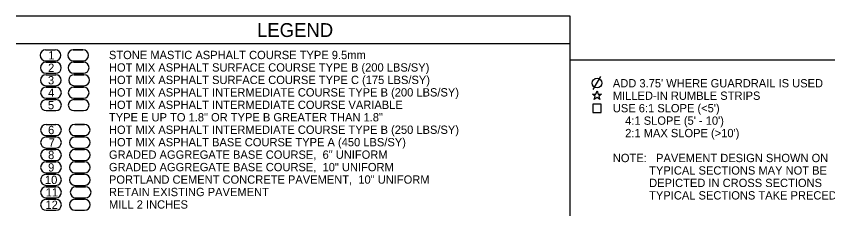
# Model space of a CAD drawing. Extents: x 2003207 to 2014043, y 843846 to 860154.
# Drawn here: x 2013805.7 to 2013864.3, y 844686 to 844700.4 of the extents above; entities that cross this region are included whole.
import ezdxf

# ---------------------------------------------------------------- set-up
doc = ezdxf.new("R2010")
doc.units = 0
for name, color, linetype in [('RD_EX_Road', 7, 'Continuous'), ('RD_EX_Road_txCode', 7, 'Continuous'), ('RD_QTY_ConcPave', 7, 'Continuous'), ('RD_QTY_Intermediate', 7, 'Continuous'), ('RD_QTY_Milling', 7, 'Continuous'), ('RD_QTY_Surf_Course', 7, 'Continuous'), ('RD_SHT_Bndy', 7, 'Continuous'), ('RD_TX_Misc2', 7, 'Continuous')]:
    doc.layers.add(name, color=color, linetype=linetype)

msp = doc.modelspace()

# ---------------------------------------------------------------- linework, layer by layer
at = {"layer": 'RD_EX_Road'}
for p, q in [((2013810.723, 844688.087), (2013810.023, 844688.087)), ((2013810.661, 844687.187), (2013809.961, 844687.187)), ((2013810.023, 844687.287), (2013810.723, 844687.287)), ((2013809.961, 844686.387), (2013810.661, 844686.387))]:
    msp.add_line(p, q, dxfattribs=at)
for centre, start, end in [((2013810.023, 844687.687), 90, 270), ((2013810.723, 844687.687), 270, 90), ((2013809.961, 844686.787), 90, 270), ((2013810.661, 844686.787), 270, 90)]:
    msp.add_arc(centre, 0.4, start, end, dxfattribs=at)
at = {"layer": 'RD_EX_Road_txCode'}
msp.add_line((2013847.384, 844695.107), (2013847.95, 844696.05), dxfattribs=at)
for points in [[(2013847.335, 844694.786), (2013847.589, 844694.786), (2013847.667, 844695.028), (2013847.746, 844694.786), (2013848, 844694.786), (2013847.795, 844694.637), (2013847.873, 844694.395), (2013847.667, 844694.544), (2013847.462, 844694.395), (2013847.54, 844694.637)], [(2013847.367, 844693.452), (2013847.967, 844693.452), (2013847.967, 844694.052), (2013847.367, 844694.052)]]:
    msp.add_lwpolyline(points, close=True, dxfattribs=at)
msp.add_circle((2013847.667, 844695.578), 0.35, dxfattribs=at)
at = {"layer": 'RD_QTY_ConcPave'}
for p, q in [((2013810.661, 844690.787), (2013809.961, 844690.787)), ((2013809.961, 844689.987), (2013810.661, 844689.987)), ((2013810.661, 844689.887), (2013809.961, 844689.887)), ((2013809.961, 844689.087), (2013810.661, 844689.087)), ((2013810.661, 844688.987), (2013809.961, 844688.987)), ((2013809.961, 844688.187), (2013810.661, 844688.187))]:
    msp.add_line(p, q, dxfattribs=at)
for centre, start, end in [((2013809.961, 844690.387), 90, 270), ((2013810.661, 844690.387), 270, 90), ((2013809.961, 844689.487), 90, 270), ((2013810.661, 844689.487), 270, 90), ((2013809.961, 844688.587), 90, 270), ((2013810.661, 844688.587), 270, 90)]:
    msp.add_arc(centre, 0.4, start, end, dxfattribs=at)
at = {"layer": 'RD_QTY_Intermediate'}
for p, q in [((2013810.582, 844695.287), (2013809.882, 844695.287)), ((2013809.882, 844694.487), (2013810.582, 844694.487)), ((2013810.582, 844694.387), (2013809.882, 844694.387)), ((2013809.882, 844693.587), (2013810.582, 844693.587)), ((2013810.65, 844692.587), (2013809.95, 844692.587)), ((2013809.95, 844691.787), (2013810.65, 844691.787)), ((2013810.661, 844691.687), (2013809.961, 844691.687)), ((2013809.961, 844690.887), (2013810.661, 844690.887))]:
    msp.add_line(p, q, dxfattribs=at)
for centre, start, end in [((2013809.882, 844694.887), 90, 270), ((2013810.582, 844694.887), 270, 90), ((2013809.882, 844693.987), 90, 270), ((2013810.582, 844693.987), 270, 90), ((2013809.95, 844692.187), 90, 270), ((2013810.65, 844692.187), 270, 90), ((2013809.961, 844691.287), 90, 270), ((2013810.661, 844691.287), 270, 90)]:
    msp.add_arc(centre, 0.4, start, end, dxfattribs=at)
at = {"layer": 'RD_QTY_Milling'}
for p, q in [((2013810.661, 844687.187), (2013809.961, 844687.187)), ((2013809.961, 844686.387), (2013810.661, 844686.387))]:
    msp.add_line(p, q, dxfattribs=at)
for centre, start, end in [((2013809.961, 844686.787), 90, 270), ((2013810.661, 844686.787), 270, 90)]:
    msp.add_arc(centre, 0.4, start, end, dxfattribs=at)
at = {"layer": 'RD_QTY_Surf_Course'}
for p, q in [((2013810.542, 844697.987), (2013809.842, 844697.987)), ((2013809.842, 844697.187), (2013810.542, 844697.187)), ((2013810.576, 844697.087), (2013809.876, 844697.087)), ((2013809.876, 844696.287), (2013810.576, 844696.287)), ((2013810.61, 844696.187), (2013809.91, 844696.187)), ((2013809.91, 844695.387), (2013810.61, 844695.387))]:
    msp.add_line(p, q, dxfattribs=at)
for centre, start, end in [((2013809.842, 844697.587), 90, 270), ((2013810.542, 844697.587), 270, 90), ((2013809.876, 844696.687), 90, 270), ((2013810.576, 844696.687), 270, 90), ((2013809.91, 844695.787), 90, 270), ((2013810.61, 844695.787), 270, 90)]:
    msp.add_arc(centre, 0.4, start, end, dxfattribs=at)
at = {"layer": 'RD_SHT_Bndy'}
for p, q in [((2013845.721, 844700.41), (2013805.721, 844700.41)), ((2013845.721, 844698.41), (2013845.721, 844700.41)), ((2013845.721, 844698.41), (2013805.721, 844698.41)), ((2013845.721, 844685.992), (2013845.721, 844698.41)), ((2013868.755, 844697.242), (2013845.755, 844697.242))]:
    msp.add_line(p, q, dxfattribs=at)
at = {"layer": 'RD_TX_Misc2'}
for p, q in [((2013807.842, 844697.987), (2013808.542, 844697.987)), ((2013809.842, 844697.987), (2013810.542, 844697.987)), ((2013807.842, 844697.187), (2013808.542, 844697.187)), ((2013807.876, 844697.087), (2013808.576, 844697.087)), ((2013809.842, 844697.187), (2013810.542, 844697.187)), ((2013809.876, 844697.087), (2013810.576, 844697.087)), ((2013807.871, 844696.187), (2013808.571, 844696.187)), ((2013807.876, 844696.287), (2013808.576, 844696.287)), ((2013809.876, 844696.287), (2013810.576, 844696.287)), ((2013809.91, 844696.187), (2013810.61, 844696.187)), ((2013807.871, 844695.387), (2013808.571, 844695.387)), ((2013807.882, 844695.287), (2013808.582, 844695.287)), ((2013809.882, 844695.287), (2013810.582, 844695.287)), ((2013809.91, 844695.387), (2013810.61, 844695.387)), ((2013807.882, 844694.487), (2013808.582, 844694.487)), ((2013807.882, 844694.387), (2013808.582, 844694.387)), ((2013809.882, 844694.487), (2013810.582, 844694.487)), ((2013809.882, 844694.387), (2013810.582, 844694.387)), ((2013807.882, 844693.587), (2013808.582, 844693.587)), ((2013809.882, 844693.587), (2013810.582, 844693.587)), ((2013807.882, 844692.587), (2013808.582, 844692.587)), ((2013809.95, 844692.587), (2013810.65, 844692.587)), ((2013807.882, 844691.787), (2013808.582, 844691.787)), ((2013807.882, 844691.687), (2013808.582, 844691.687)), ((2013809.95, 844691.787), (2013810.65, 844691.787)), ((2013809.961, 844691.687), (2013810.661, 844691.687)), ((2013807.882, 844690.887), (2013808.582, 844690.887)), ((2013807.882, 844690.787), (2013808.582, 844690.787)), ((2013809.961, 844690.887), (2013810.661, 844690.887)), ((2013809.961, 844690.787), (2013810.661, 844690.787)), ((2013807.882, 844689.987), (2013808.582, 844689.987)), ((2013807.882, 844689.887), (2013808.582, 844689.887)), ((2013809.961, 844689.987), (2013810.661, 844689.987)), ((2013809.961, 844689.887), (2013810.661, 844689.887)), ((2013807.882, 844689.087), (2013808.582, 844689.087)), ((2013807.882, 844688.987), (2013808.582, 844688.987)), ((2013809.961, 844689.087), (2013810.661, 844689.087)), ((2013809.961, 844688.987), (2013810.661, 844688.987)), ((2013807.882, 844688.187), (2013808.582, 844688.187)), ((2013809.961, 844688.187), (2013810.661, 844688.187)), ((2013807.882, 844688.087), (2013808.582, 844688.087)), ((2013810.023, 844688.087), (2013810.723, 844688.087)), ((2013807.882, 844687.287), (2013808.582, 844687.287)), ((2013807.882, 844687.187), (2013808.582, 844687.187)), ((2013809.961, 844687.187), (2013810.661, 844687.187)), ((2013810.023, 844687.287), (2013810.723, 844687.287)), ((2013807.882, 844686.387), (2013808.582, 844686.387)), ((2013809.961, 844686.387), (2013810.661, 844686.387))]:
    msp.add_line(p, q, dxfattribs=at)
for centre, start, end in [((2013807.842, 844697.587), 90, 270), ((2013808.542, 844697.587), 270, 90), ((2013809.842, 844697.587), 90, 270), ((2013810.542, 844697.587), 270, 90), ((2013807.876, 844696.687), 90, 270), ((2013808.576, 844696.687), 270, 90), ((2013809.876, 844696.687), 90, 270), ((2013810.576, 844696.687), 270, 90), ((2013807.871, 844695.787), 90, 270), ((2013808.571, 844695.787), 270, 90), ((2013809.91, 844695.787), 90, 270), ((2013810.61, 844695.787), 270, 90), ((2013807.882, 844694.887), 90, 270), ((2013808.582, 844694.887), 270, 90), ((2013809.882, 844694.887), 90, 270), ((2013810.582, 844694.887), 270, 90), ((2013807.882, 844693.987), 90, 270), ((2013808.582, 844693.987), 270, 90), ((2013809.882, 844693.987), 90, 270), ((2013810.582, 844693.987), 270, 90), ((2013807.882, 844692.187), 90, 270), ((2013808.582, 844692.187), 270, 90), ((2013809.95, 844692.187), 90, 270), ((2013810.65, 844692.187), 270, 90), ((2013807.882, 844691.287), 90, 270), ((2013808.582, 844691.287), 270, 90), ((2013809.961, 844691.287), 90, 270), ((2013810.661, 844691.287), 270, 90), ((2013807.882, 844690.387), 90, 270), ((2013808.582, 844690.387), 270, 90), ((2013809.961, 844690.387), 90, 270), ((2013810.661, 844690.387), 270, 90), ((2013807.882, 844689.487), 90, 270), ((2013808.582, 844689.487), 270, 90), ((2013809.961, 844689.487), 90, 270), ((2013810.661, 844689.487), 270, 90), ((2013807.882, 844688.587), 90, 270), ((2013808.582, 844688.587), 270, 90), ((2013809.961, 844688.587), 90, 270), ((2013810.661, 844688.587), 270, 90), ((2013807.882, 844687.687), 90, 270), ((2013808.582, 844687.687), 270, 90), ((2013810.023, 844687.687), 90, 270), ((2013810.723, 844687.687), 270, 90), ((2013807.882, 844686.787), 90, 270), ((2013808.582, 844686.787), 270, 90), ((2013809.961, 844686.787), 90, 270), ((2013810.661, 844686.787), 270, 90)]:
    msp.add_arc(centre, 0.4, start, end, dxfattribs=at)

# ---------------------------------------------------------------- texts
at = {"layer": 'RD_EX_Road_txCode'}
for s, height, p in [('LEGEND', 1, (2013823.11, 844698.91)), ('STONE MASTIC ASPHALT COURSE TYPE 9.5mm', 0.6, (2013812.417, 844697.31)), ('HOT MIX ASPHALT SURFACE COURSE TYPE B (200 LBS/SY)', 0.6, (2013812.417, 844696.41)), ('HOT MIX ASPHALT SURFACE COURSE TYPE C (175 LBS/SY)', 0.6, (2013812.417, 844695.51)), ("ADD 3.75' WHERE GUARDRAIL IS USED", 0.6, (2013848.808, 844695.268)), ('HOT MIX ASPHALT INTERMEDIATE COURSE TYPE B (200 LBS/SY)', 0.6, (2013812.417, 844694.61)), ('MILLED-IN RUMBLE STRIPS', 0.6, (2013848.808, 844694.368)), ('HOT MIX ASPHALT INTERMEDIATE COURSE VARIABLE ', 0.6, (2013812.417, 844693.71)), ("USE 6:1 SLOPE (<5')", 0.6, (2013848.808, 844693.468)), ('TYPE E UP TO 1.8" OR TYPE B GREATER THAN 1.8"', 0.6, (2013812.417, 844692.81)), ("    4:1 SLOPE (5' - 10')", 0.6, (2013848.808, 844692.568)), ('HOT MIX ASPHALT INTERMEDIATE COURSE TYPE B (250 LBS/SY)', 0.6, (2013812.417, 844691.91)), ("    2:1 MAX SLOPE (>10')", 0.6, (2013848.808, 844691.668)), ('HOT MIX ASPHALT BASE COURSE TYPE A (450 LBS/SY)', 0.6, (2013812.417, 844691.01)), ('GRADED AGGREGATE BASE COURSE,  6" UNIFORM', 0.6, (2013812.417, 844690.11)), ('NOTE:   PAVEMENT DESIGN SHOWN ON', 0.6, (2013848.808, 844689.868)), ('GRADED AGGREGATE BASE COURSE,  10" UNIFORM', 0.6, (2013812.417, 844689.21)), (' TYPICAL SECTIONS MAY NOT BE ', 0.6, (2013851.208, 844688.968)), ('PORTLAND CEMENT CONCRETE PAVEMENT,  10" UNIFORM', 0.6, (2013812.417, 844688.31)), (' DEPICTED IN CROSS SECTIONS', 0.6, (2013851.208, 844688.068)), ('RETAIN EXISTING PAVEMENT', 0.6, (2013812.417, 844687.41)), (' TYPICAL SECTIONS TAKE PRECEDENCE', 0.6, (2013851.208, 844687.168)), ('MILL 2 INCHES', 0.6, (2013812.417, 844686.51))]:
    msp.add_text(s, height=height, dxfattribs=at).set_placement(p)
at = {"layer": 'RD_TX_Misc2'}
for s, p in [('1', (2013808.039, 844697.287)), ('2', (2013808.022, 844696.387)), ('3', (2013808.011, 844695.487)), ('4', (2013808.023, 844694.587)), ('5', (2013808.011, 844693.687)), ('6', (2013808.023, 844691.887)), ('7 ', (2013808.066, 844690.987)), ('8', (2013808.023, 844690.087)), ('9', (2013808.023, 844689.187)), ('10', (2013807.796, 844688.287)), ('11', (2013807.852, 844687.387)), ('12', (2013807.835, 844686.487))]:
    msp.add_text(s, height=0.6, dxfattribs=at).set_placement(p)

doc.saveas('drawing.dxf')
